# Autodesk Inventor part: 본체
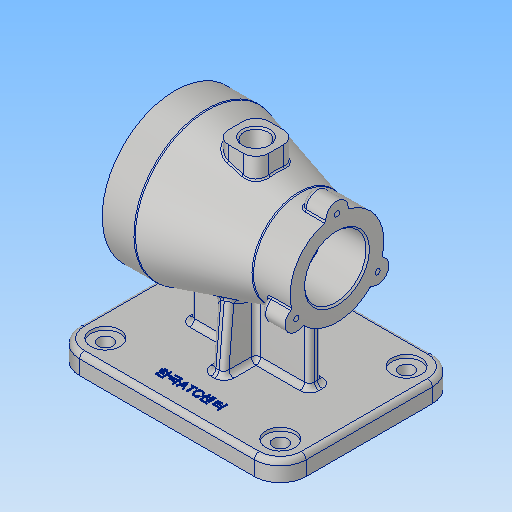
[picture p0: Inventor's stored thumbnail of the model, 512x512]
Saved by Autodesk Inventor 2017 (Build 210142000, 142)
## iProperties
Part Number: 본체
Material: 알루미늄 6061
Document SubType Name: Modeling
Designer: user
Density: 2.7 g/cm^3
Appearance: 알루미늄 - 평지
Mass: 1223.12 g
Surface Area: 899.626 cm^2
Volume: 453.008 cm^3
Author: user
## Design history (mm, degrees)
sketch "스케치1"
  geometry: L1 (-50, 0)-(50, 0); L2 (-50, 45)-(-30.413, 45); L3 (-29.602, 44.888)-(26.602, 29.112); L4 (27.413, 29)-(50, 29); L5 (50, 29)-(50, 19); L6 (50, 19)-(23, 19); L7 (20, 22)-(20, 22); L8 (17, 25)-(-24, 25); L9 (-27, 28)-(-27, 28); L10 (-30, 31)-(-50, 31); L11 (-50, 31)-(-50, 45); L12 (27.413, -29)-(50, -29); A1 r 3 centre (-30, 28) between (-27, 28) and (-30, 31); A2 r 3 centre (-24, 28) between (-27, 28) and (-24, 25); A3 r 3 centre (17, 22) between (20, 22) and (17, 25); A4 r 3 centre (23, 22) between (20, 22) and (23, 19); A5 r 3 centre (-30.413, 42) between (-29.602, 44.888) and (-30.413, 45); A6 r 3 centre (27.413, 32) between (26.602, 29.112) and (27.413, 29); 7 further points
  constraints: 24 end point, 12 point on circle, 12 tangent, 10 point on line, 7 perpendicular, 6 centre point, 5 equal radius, 2 horizontal, 2 symmetric about line, 2 vertical alignment, 1 coincident, 1 midpoint, 1 parallel
  dimensions: "d0" = 100 distance of L1.start L1.end; "d1" = 20 distance of L2.start point (-30, 45); "d2" = 23 distance of point (27, 29) L4.end; "d3" = 90 diameter of L2 L1; "d4" = 62 diameter of L10 L1; "d5" = 23 distance of point (-27, 31) L10.end; "d6" = 47 distance of point (20, 25) point (-27, 25); "d7" = 50 diameter of L8 L1; "d8" = 38 diameter of L6 L1; "d9" = 58 diameter of L4 L1; "d10" = 3 radius of A1; "d94" = 58 diameter of L12 L1 (derived)
revolve "회전1" sketch "스케치1" stored, may be unused: angle "d11" = 90 deg
sketch "스케치2" dims "d12" = 80
  geometry: L1 (0, 40)-(34.641, 20); L2 (34.641, 20)-(34.641, -20); L3 (34.641, -20)-(0, -40); L4 (0, -40)-(-34.641, -20); L5 (-34.641, -20)-(-34.641, 20); L6 (-34.641, 20)-(0, 40); C1 r 31 at (0, 0) reference; 8 further points
  constraints: 12 end point, 8 coincident, 1 vertical, 1 vertical alignment, 15 other
hole "구멍1" sketch "스케치2" at (0, 40), (34.641, 20), (34.641, -20), (0, -40), (-34.641, -20), (-34.641, 20) diameter "d13" = 3.242; stored, may be unused: countersink angle "d17" = 90 deg, drill point angle "d19" = 118 deg; dims "d14" = 9, "d15" = 4, "d16" = 2, "d18" = 11
sketch "스케치3"
  geometry: L1 (0, 29)-(25.115, -14.5); L2 (25.115, -14.5)-(-25.115, -14.5); L3 (-25.115, -14.5)-(0, 29); C1 r 7 at (0, 29); C2 r 7 at (25.115, -14.5); C3 r 7 at (-25.115, -14.5); 2 further points
  constraints: 6 end point, 4 coincident, 3 centre point, 1 horizontal, 1 vertical alignment, 8 other
  dimensions: "d20" = 14 diameter of C2; "d22" = 14 diameter of C1; "d23" = 14 diameter of C3
extrude "돌출1" join sketch "스케치3" distance "d24" = 15; taper "d25" = 0 deg
sketch "스케치4"
  geometry: A1 r 7 centre (25.115, -43.5) between (20.909, -49.095) and (27.858, -37.06) reference; A2 r 7 centre (0, 0) between (6.949, -0.845) and (-6.949, -0.845) reference; A3 r 7 centre (-25.115, -43.5) between (-27.858, -37.06) and (-20.909, -49.095) reference; 3 further points
  constraints: 3 coincident
hole "구멍2" sketch "스케치4" at (0, 0), (-25.115, -43.5), (25.115, -43.5) diameter "d26" = 3.242; stored, may be unused: countersink angle "d30" = 90 deg, drill point angle "d32" = 118 deg; dims "d27" = 9, "d28" = 4, "d29" = 2, "d31" = 11
node "작업 평면1"
sketch "스케치5"
  geometry: L1 (-4.5, -12.5)-(4.5, -12.5); L2 (12.5, -4.5)-(12.5, 4.5); L3 (4.5, 12.5)-(-4.5, 12.5); L4 (-12.5, 4.5)-(-12.5, -4.5); L5 (-12.5, -12.5)-(12.5, 12.5); L6 (12.5, -12.5)-(-12.5, 12.5); L7 (50, 45)-(50, -45) reference; A1 r 8 centre (-4.5, -4.5) between (-12.5, -4.5) and (-4.5, -12.5); A2 r 8 centre (-4.5, 4.5) between (-4.5, 12.5) and (-12.5, 4.5); A3 r 8 centre (4.5, 4.5) between (12.5, 4.5) and (4.5, 12.5); A4 r 8 centre (4.5, -4.5) between (4.5, -12.5) and (12.5, -4.5); 3 further points
  constraints: 12 end point, 8 point on circle, 8 point on line, 8 tangent, 4 centre point, 3 equal radius, 3 midpoint, 2 parallel, 1 coincident, 1 horizontal, 1 perpendicular
  dimensions: "d34" = 25 distance of L6.end L5.end; "d35" = 25 distance of L5.end L6.start; "d36" = 8 radius of A1; "d37" = 50 distance from line of L7 point (0, 0)
extrude "돌출2" join sketch "스케치5" stored distance "d38" = 15; taper "d39" = 0 deg
sketch "스케치6"
  geometry: 2 further points
  constraints: 1 coincident
hole "구멍3" sketch "스케치6" at (0, 0) diameter "d40" = 15; stored, may be unused: countersink angle "d44" = 90 deg, drill point angle "d46" = 118 deg; dims "d41" = 9, "d42" = 4, "d43" = 2, "d45" = 15
node "작업 평면2"
sketch "스케치7"
  geometry: L1 (-54, 55)-(54, 55); L2 (70, 39)-(70, -39); L3 (54, -55)-(-54, -55); L4 (-70, -39)-(-70, 39); L5 (-70, 55)-(70, -55); L6 (70, 55)-(-70, -55); A1 r 16 centre (54, 39) between (70, 39) and (54, 55); A2 r 16 centre (-54, 39) between (-54, 55) and (-70, 39); A3 r 16 centre (-54, -39) between (-70, -39) and (-54, -55); A4 r 16 centre (54, -39) between (54, -55) and (70, -39); 1 further point
  constraints: 12 end point, 8 point on circle, 8 point on line, 8 tangent, 4 centre point, 3 equal radius, 2 midpoint, 2 parallel, 1 horizontal, 1 perpendicular
  dimensions: "d48" = 140 distance of L5.end L6.end; "d49" = 110 distance of L6.start L5.end; "d50" = 16 radius of A1
extrude "돌출3" join sketch "스케치7" distance "d51" = 12; taper "d52" = 0 deg
sketch "스케치8"
  geometry: L1 (54, 55)-(-54, 55) reference; L2 (-70, 39)-(-70, -39) reference; 5 further points
  constraints: 2 horizontal alignment, 2 vertical alignment
  dimensions: "d53" = 16 distance from line of L2 point (-54, 39); "d54" = 108 distance of point (54, 39) point (-54, 39); "d55" = 16 distance from line of L1 point (-54, 39); "d56" = 78 distance of point (-54, -39) point (-54, 39)
hole "구멍4" sketch "스케치8" at (-54, 39), (54, 39), (54, -39), (-54, -39) diameter "d57" = 9; stored, may be unused: countersink angle "d61" = 90 deg, drill point angle "d63" = 118 deg; dims "d58" = 9, "d59" = 18, "d60" = 2, "d62" = 15
sketch "스케치9"
  geometry: L1 (-70, 39)-(-70, -39) reference; L2 (-37, 4)-(37, 4); L3 (37, 4)-(37, -4); L4 (37, -4)-(-37, -4); L5 (-37, -4)-(-37, 4); L6 (-37, 4)-(37, -4); L7 (37, 4)-(-37, -4); 3 further points
  constraints: 12 end point, 3 midpoint, 2 parallel, 1 coincident, 1 horizontal, 1 perpendicular
  dimensions: "d64" = 74 distance of L3.end L4.end; "d65" = 8 distance of L2.end L3.end; "d66" = 33 distance between parallel lines of L5 L1
extrude "돌출4" join sketch "스케치9" stored distance "d67" = 12; taper "d68" = 0 deg
sketch "스케치10"
  geometry: L1 (45, 7.5)-(23.848, 7.5) reference; L2 (23.848, -7.5)-(45, -7.5) reference; L3 (45, -7.5)-(45, -12.5) reference; L4 (45, -12.5)-(34.377, -12.5) reference; L5 (-36.36, -4)-(-70, -4) reference; L6 (-70, -4)-(-70, -55) reference; L7 (-70, -55)-(-82, -55) reference; L8 (-82, -55)-(-82, 55) reference; L9 (-82, 55)-(-70, 55) reference; L10 (-70, 55)-(-70, 4) reference; L11 (-70, 4)-(-36.36, 4) reference; L12 (34.377, 12.5)-(45, 12.5) reference; L13 (45, 12.5)-(45, 7.5) reference; L14 (-70, -24)-(-30.278, -20.525); L15 (-30.278, 20.525)-(-70, 24); A1 r 25 centre (0, 0) between (23.848, 7.5) and (23.848, -7.5) reference; A2 r 36.579 centre (0, 0) between (-36.36, -4) and (34.377, -12.5) reference; A3 r 36.579 centre (0, 0) between (34.377, 12.5) and (-36.36, 4) reference; 1 further point
  constraints: 4 end point, 2 point on circle, 2 point on line
  dimensions: "d69" = 24 vertical distance of point (0, 0) L14.start; "d70" = 24 vertical distance of L15.end point (0, 0); "d71" = 95 deg angle of L6 L14; "d73" = 95 deg angle of L10 L15
  node "절단 모서리 투영1"
feature "리브1" dims "d74" = 1, "d75" = 8, "d76" = 0, "d77" = 0, "d78" = 1, "d79" = 1
feature "리브2" dims "d80" = 1, "d81" = 8, "d82" = 0, "d83" = 0, "d84" = 1, "d85" = 1
fillet "모깎기1" dims "d86" = 3
fillet "모깎기2" dims "d87" = 1
chamfer "모따기1" distance "d88" = 1; stored, may be unused: second distance "d89" = 2, angle "d90" = 45 deg
sketch "스케치11"
  geometry: L1 (-54, -55)-(54, -55) reference; 2 further points
  constraints: 1 vertical alignment, 1 other
  dimensions: "d91" = 15 distance from line of point (0, -40) L1
feature "엠보싱1" sketch "스케치11" dims "d0" = 100, "d1" = 20, "d2" = 23, "d3" = 90, "d4" = 62, "d5" = 23, "d6" = 47, "d7" = 50, "d8" = 38, "d9" = 58, "d10" = 3, "d92" = 0.5, "d93" = 0, "d94" = 58 (derived)
node "솔리드1"
other parameters: "d33" = 45, "d47" = -82
